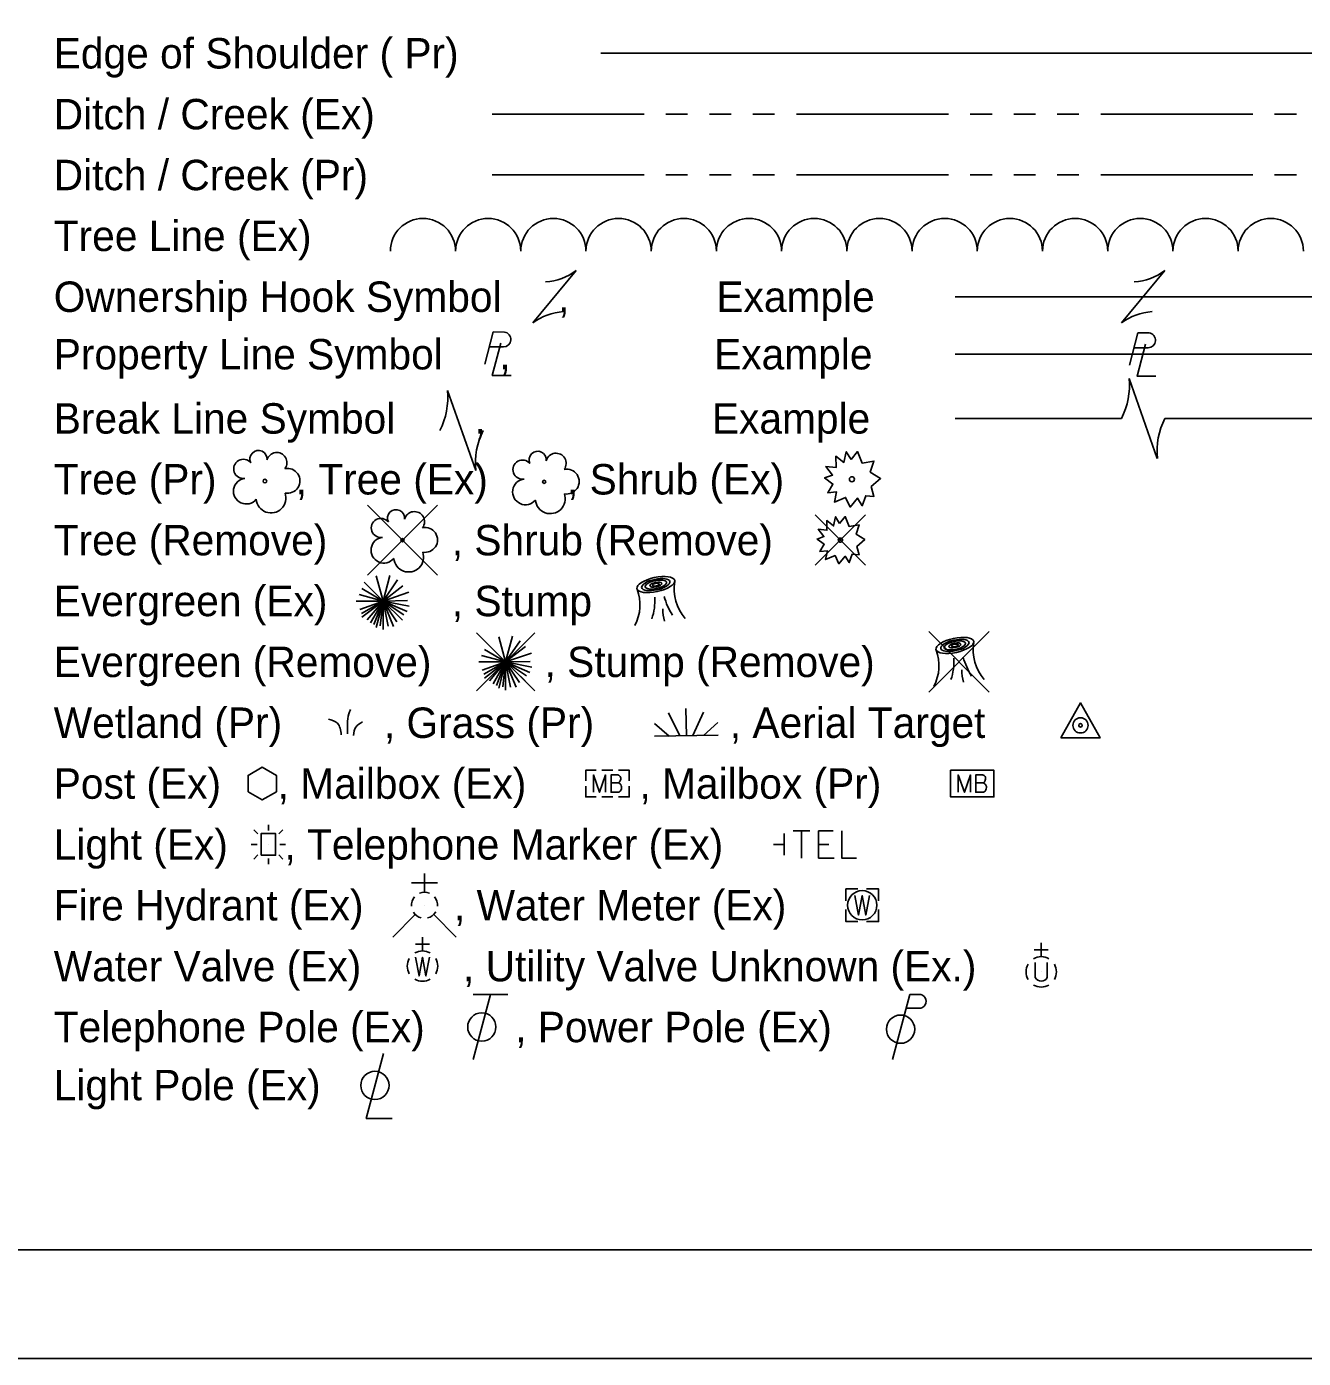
# Model space of a CAD drawing. Extents: x 0 to 34, y 0 to 22.
# Drawn here: x 8.61 to 14.48, y 0 to 6.13 of the extents above; entities that cross this region are included whole.
import ezdxf

# ---------------------------------------------------------------- set-up
doc = ezdxf.new("R2010")
doc.units = 0
for name, color, linetype in [('SH_Border', 7, 'Continuous'), ('SH_Cut_Line', 7, 'Continuous'), ('SH_Text', 7, 'Continuous')]:
    doc.layers.add(name, color=color, linetype=linetype)

msp = doc.modelspace()

# ---------------------------------------------------------------- linework, layer by layer
at = {"layer": 'SH_Border'}
msp.add_lwpolyline([(1.5, 21.5), (33.5, 21.5), (33.5, 0.5), (1.5, 0.5)], close=True, dxfattribs=at)
at = {"layer": 'SH_Cut_Line'}
msp.add_lwpolyline([(0, 0), (34, 0), (34, 22), (0, 22)], close=True, dxfattribs=at)
at = {"layer": 'SH_Text'}
for p, q in [((11.2493, 6.0046), (14.7327, 6.0046)), ((10.7489, 5.7246), (11.4489, 5.7246)), ((11.5489, 5.7246), (11.6489, 5.7246)), ((11.7489, 5.7246), (11.8489, 5.7246)), ((11.9489, 5.7246), (12.0489, 5.7246)), ((12.1489, 5.7246), (12.8489, 5.7246)), ((12.9489, 5.7246), (13.0489, 5.7246)), ((13.1489, 5.7246), (13.2489, 5.7246)), ((13.3489, 5.7246), (13.4489, 5.7246)), ((13.5489, 5.7246), (14.2489, 5.7246)), ((14.3489, 5.7246), (14.4489, 5.7246)), ((10.7489, 5.4446), (11.4489, 5.4446)), ((11.5489, 5.4446), (11.6489, 5.4446)), ((11.7489, 5.4446), (11.8489, 5.4446)), ((11.9489, 5.4446), (12.0489, 5.4446)), ((12.1489, 5.4446), (12.8489, 5.4446)), ((12.9489, 5.4446), (13.0489, 5.4446)), ((13.1489, 5.4446), (13.2489, 5.4446)), ((13.3489, 5.4446), (13.4489, 5.4446)), ((13.5489, 5.4446), (14.2489, 5.4446)), ((14.3489, 5.4446), (14.4489, 5.4446)), ((10.9362, 4.7646), (11.1362, 5.0046)), ((13.6444, 4.7646), (13.8444, 5.0046)), ((11.0362, 4.8846), (11.0362, 4.8846)), ((12.879, 4.8846), (14.6613, 4.8846)), ((13.7444, 4.8846), (13.7444, 4.8846)), ((10.7365, 4.6536), (10.8013, 4.6536)), ((10.7766, 4.6224), (10.7766, 4.6224)), ((12.879, 4.62), (14.6613, 4.62)), ((13.7021, 4.6495), (13.767, 4.6495)), ((13.7422, 4.6183), (13.7422, 4.6183)), ((13.6794, 4.5088), (13.8094, 4.1405)), ((10.5438, 4.4531), (10.6738, 4.0849)), ((12.879, 4.3246), (13.6445, 4.3246)), ((13.7444, 4.3247), (13.7444, 4.3247)), ((13.8444, 4.3246), (14.6613, 4.3246)), ((10.6088, 4.269), (10.6088, 4.269)), ((10.1766, 3.9249), (10.4974, 3.6042)), ((10.4974, 3.9249), (10.1766, 3.6042)), ((12.2357, 3.8805), (12.4675, 3.6487)), ((12.4675, 3.8805), (12.2357, 3.6487)), ((10.337, 3.7646), (10.337, 3.7646)), ((12.3516, 3.7646), (12.3516, 3.7646)), ((10.2475, 3.4844), (10.1602, 3.5715)), ((10.2475, 3.4844), (10.2166, 3.5997)), ((10.2475, 3.4844), (10.2789, 3.6018)), ((10.2475, 3.4844), (10.3139, 3.5815)), ((10.2475, 3.4844), (10.3389, 3.5545)), ((10.2475, 3.4844), (10.1372, 3.5139)), ((10.2475, 3.4844), (10.1498, 3.5418)), ((10.2475, 3.4844), (10.3659, 3.5245)), ((10.1241, 3.4844), (10.2475, 3.4844)), ((10.2475, 3.4844), (10.1402, 3.4453)), ((10.2475, 3.4844), (10.1479, 3.4273)), ((10.2475, 3.4844), (10.1498, 3.4095)), ((10.2475, 3.4844), (10.1739, 3.3977)), ((10.2475, 3.4844), (10.1895, 3.384)), ((10.2475, 3.4844), (10.2059, 3.3759)), ((10.2475, 3.4844), (10.2159, 3.3629)), ((10.2475, 3.4844), (10.2339, 3.3696)), ((10.2475, 3.4844), (10.3602, 3.4867)), ((10.2475, 3.3534), (10.2475, 3.4844)), ((10.2475, 3.4844), (10.2705, 3.3684)), ((10.2475, 3.4844), (10.2958, 3.3677)), ((10.2475, 3.4844), (10.3109, 3.3895)), ((10.2475, 3.4844), (10.3372, 3.3963)), ((10.2475, 3.4844), (10.343, 3.4205)), ((10.2475, 3.4844), (10.3591, 3.4358)), ((10.2475, 3.4844), (10.3682, 3.4604)), ((11.5211, 3.4846), (11.5211, 3.4846)), ((10.6779, 3.3382), (10.9452, 3.0709)), ((10.9452, 3.3382), (10.6779, 3.0709)), ((10.8115, 3.2046), (10.7806, 3.3199)), ((10.8115, 3.2046), (10.8429, 3.3221)), ((12.7577, 3.3436), (13.0358, 3.0655)), ((13.0358, 3.3436), (12.7577, 3.0655)), ((10.8115, 3.2046), (10.7138, 3.262)), ((10.8115, 3.2046), (10.7242, 3.2918)), ((10.8115, 3.2046), (10.8779, 3.3017)), ((10.8115, 3.2046), (10.9029, 3.2747)), ((10.6881, 3.2046), (10.8115, 3.2046)), ((10.8115, 3.2046), (10.7012, 3.2342)), ((10.8115, 3.2046), (10.7042, 3.1656)), ((10.8115, 3.2046), (10.7119, 3.1476)), ((10.8115, 3.2046), (10.7138, 3.1297)), ((10.8115, 3.2046), (10.7379, 3.1179)), ((10.8115, 3.2046), (10.7535, 3.1042)), ((10.8115, 3.2046), (10.7699, 3.0961)), ((10.8115, 3.2046), (10.7799, 3.0832)), ((10.8115, 3.2046), (10.798, 3.0898)), ((10.8115, 3.2046), (10.9299, 3.2448)), ((10.8115, 3.2046), (10.9242, 3.2069)), ((10.8115, 3.0736), (10.8115, 3.2046)), ((10.8115, 3.2046), (10.8345, 3.0887)), ((10.8115, 3.2046), (10.8598, 3.0879)), ((10.8115, 3.2046), (10.8749, 3.1098)), ((10.8115, 3.2046), (10.9012, 3.1166)), ((10.8115, 3.2046), (10.907, 3.1407)), ((10.8115, 3.2046), (10.9231, 3.1561)), ((10.8115, 3.2046), (10.9322, 3.1806)), ((10.8115, 3.2046), (10.8115, 3.2046)), ((12.8967, 3.2046), (12.8967, 3.2046)), ((12.8967, 3.2046), (12.8967, 3.2046)), ((11.6131, 2.8642), (11.561, 2.9702)), ((11.6431, 2.8646), (11.6412, 2.9901)), ((11.6731, 2.865), (11.722, 2.9726)), ((11.5644, 2.8634), (11.4961, 2.9205)), ((11.7218, 2.8658), (11.7884, 2.9249)), ((11.497, 2.8624), (11.7892, 2.8668)), ((11.2543, 2.7057), (11.3044, 2.7057)), ((11.2799, 2.6446), (11.2799, 2.6446)), ((12.958, 2.6446), (12.958, 2.6446)), ((11.2543, 2.5835), (11.3044, 2.5835)), ((9.7202, 2.4286), (9.7202, 2.4552)), ((9.6719, 2.413), (9.6534, 2.4318)), ((9.7869, 2.4318), (9.7683, 2.413)), ((12.0928, 2.3146), (12.0928, 2.4146)), ((9.668, 2.3649), (9.6414, 2.3649)), ((9.7202, 2.3646), (9.7202, 2.3646)), ((9.7989, 2.3649), (9.7723, 2.3649)), ((12.0928, 2.3646), (12.0431, 2.3646)), ((9.6719, 2.3162), (9.6534, 2.2974)), ((9.7202, 2.3006), (9.7202, 2.274)), ((9.7869, 2.2974), (9.7683, 2.3162)), ((10.4382, 2.1448), (10.4382, 2.2308)), ((10.4982, 2.1878), (10.3782, 2.1878)), ((10.4383, 2.0846), (10.4383, 2.0846)), ((10.4383, 2.0846), (10.4383, 2.0846)), ((12.4519, 2.0846), (12.4519, 2.0846)), ((10.396, 2.0422), (10.292, 1.9383)), ((10.4806, 2.0422), (10.5846, 1.9383)), ((10.4609, 1.9064), (10.3973, 1.9064)), ((10.4292, 1.8746), (10.4292, 1.9382)), ((13.2753, 1.8482), (13.2753, 1.9117)), ((13.3071, 1.88), (13.2435, 1.88)), ((10.4292, 1.8046), (10.4292, 1.8046)), ((13.2481, 1.8213), (13.2481, 1.7524)), ((13.2753, 1.7782), (13.2753, 1.7782)), ((13.3024, 1.8213), (13.3024, 1.7524)), ((10.7422, 1.6746), (10.6619, 1.3746)), ((10.8222, 1.6746), (10.6622, 1.6746)), ((12.6712, 1.6746), (12.5908, 1.3746)), ((12.6712, 1.6746), (12.7137, 1.6746)), ((12.6541, 1.6108), (12.7137, 1.6108))]:
    msp.add_line(p, q, dxfattribs=at)
for points in [[(10.7155, 4.574), (10.7546, 4.7223), (10.8063, 4.7222)], [(13.6811, 4.5699), (13.7202, 4.7182), (13.7719, 4.7181)], [(10.7899, 4.6704), (10.7503, 4.5226), (10.8377, 4.5226)], [(13.7556, 4.6663), (13.716, 4.5185), (13.8033, 4.5185)], [(12.4003, 4.1351), (12.4306, 4.1718), (12.4513, 4.1192), (12.5059, 4.1282), (12.489, 4.0776), (12.5363, 4.0478), (12.4934, 4.0111), (12.5059, 3.9654), (12.4683, 3.9688), (12.452, 3.9232), (12.4306, 3.9578), (12.3967, 3.9169), (12.3753, 3.9613), (12.3243, 3.9398), (12.3338, 3.9868), (12.2933, 3.9827), (12.3169, 4.0222), (12.2785, 4.0506), (12.3154, 4.0638), (12.2851, 4.1039), (12.3317, 4.0984), (12.3302, 4.1503), (12.3678, 4.1219), (12.3782, 4.1712), (12.4003, 4.1351)], [(12.348, 3.8415), (12.3737, 3.8728), (12.3913, 3.828), (12.4377, 3.8356), (12.4234, 3.7926), (12.4635, 3.7674), (12.4271, 3.7361), (12.4377, 3.6973), (12.4057, 3.7002), (12.3919, 3.6614), (12.3737, 3.6908), (12.3449, 3.6561), (12.3267, 3.6938), (12.2833, 3.6755), (12.2915, 3.7155), (12.257, 3.712), (12.2771, 3.7455), (12.2444, 3.7697), (12.2758, 3.7809), (12.25, 3.815), (12.2896, 3.8104), (12.2884, 3.8545), (12.3204, 3.8303), (12.3292, 3.8722), (12.348, 3.8415)], [(9.627, 2.6071), (9.6919, 2.5696), (9.7568, 2.6071), (9.7568, 2.6821), (9.6919, 2.7196), (9.627, 2.6821), (9.627, 2.6071)], [(11.1799, 2.6572), (11.1799, 2.7057), (11.2284, 2.7057)], [(11.3302, 2.7057), (11.3799, 2.7057), (11.3799, 2.6572)], [(11.215, 2.6046), (11.215, 2.6846), (11.244, 2.6046), (11.2717, 2.6846), (11.2717, 2.6046)], [(11.3309, 2.6481), (11.3341, 2.6512), (11.336, 2.6531), (11.3372, 2.655), (11.3379, 2.6562), (11.3391, 2.6588), (11.3398, 2.6607), (11.341, 2.6651), (11.341, 2.667), (11.341, 2.6695), (11.3404, 2.6733), (11.3391, 2.6764), (11.3372, 2.6789), (11.3341, 2.6814), (11.3316, 2.6827), (11.3303, 2.6833), (11.3272, 2.6846), (11.2963, 2.6846), (11.2963, 2.6046), (11.3309, 2.6046), (11.3353, 2.6071), (11.3391, 2.6103), (11.3423, 2.6153), (11.3442, 2.621), (11.3448, 2.6266), (11.3448, 2.6304), (11.3435, 2.6342), (11.341, 2.6399), (11.3379, 2.6436), (11.3309, 2.6481), (11.2963, 2.6481)], [(12.8932, 2.6046), (12.8932, 2.6846), (12.9221, 2.6046), (12.9498, 2.6846), (12.9498, 2.6046)], [(13.0091, 2.6481), (13.0122, 2.6512), (13.0141, 2.6531), (13.0154, 2.655), (13.016, 2.6562), (13.0173, 2.6588), (13.0179, 2.6607), (13.0191, 2.6651), (13.0191, 2.667), (13.0191, 2.6695), (13.0185, 2.6733), (13.0173, 2.6764), (13.0154, 2.6789), (13.0122, 2.6814), (13.0097, 2.6827), (13.0084, 2.6833), (13.0053, 2.6846), (12.9744, 2.6846), (12.9744, 2.6046), (13.0091, 2.6046), (13.0135, 2.6071), (13.0173, 2.6103), (13.0204, 2.6153), (13.0223, 2.621), (13.0229, 2.6266), (13.0229, 2.6304), (13.0217, 2.6342), (13.0191, 2.6399), (13.016, 2.6436), (13.0091, 2.6481), (12.9744, 2.6481)], [(11.2284, 2.5835), (11.1799, 2.5835), (11.1799, 2.632)], [(11.3799, 2.632), (11.3799, 2.5835), (11.3302, 2.5835)], [(12.1337, 2.4267), (12.2114, 2.4267)], [(12.173, 2.4267), (12.173, 2.3017)], [(12.3187, 2.4267), (12.2508, 2.4267), (12.2508, 2.3017), (12.3236, 2.3017)], [(12.358, 2.4267), (12.358, 2.3017), (12.426, 2.3017)], [(12.2508, 2.3647), (12.299, 2.3647)], [(12.4319, 2.1596), (12.3769, 2.1596), (12.3769, 2.1046)], [(12.5269, 2.1046), (12.5269, 2.1596), (12.4719, 2.1596)], [(12.4185, 2.1296), (12.4352, 2.0396), (12.4519, 2.1296), (12.4685, 2.0396), (12.4852, 2.1296)], [(12.3769, 2.0646), (12.3769, 2.0096), (12.4319, 2.0096)], [(12.4719, 2.0096), (12.5269, 2.0096), (12.5269, 2.0646)], [(10.3973, 1.8456), (10.4132, 1.7594), (10.4292, 1.8456), (10.4452, 1.7594), (10.461, 1.8456)], [(10.2494, 1.4033), (10.1707, 1.1041), (10.2889, 1.1041)]]:
    msp.add_lwpolyline(points, dxfattribs=at)
for points in [[(13.3661, 2.8546), (13.5461, 2.8546), (13.4561, 3.0156)], [(12.858, 2.7057), (13.058, 2.7057), (13.058, 2.5835), (12.858, 2.5835)], [(9.6869, 2.3146), (9.7534, 2.3146), (9.7534, 2.4146), (9.6869, 2.4146)]]:
    msp.add_lwpolyline(points, close=True, dxfattribs=at)
for centre, radius in [((9.704, 4.0365), 0.0084), ((12.4046, 4.0446), 0.0115), ((10.9886, 4.033), 0.0072), ((10.337, 3.7646), 0.0072), ((12.3516, 3.7646), 0.00979), ((13.4561, 2.9124), 0.035), ((13.4561, 2.9124), 0.008), ((12.4519, 2.0846), 0.0675), ((10.702, 1.5246), 0.065), ((12.6283, 1.5146), 0.065), ((10.2101, 1.2557), 0.065)]:
    msp.add_circle(centre, radius, dxfattribs=at)
for centre, radius, start, end in [((10.4312, 5.0946), 0.15, 0.00982, 179.99264), ((10.7312, 5.0946), 0.15, 0.00982, 179.99264), ((11.0312, 5.0946), 0.15, 0.00982, 179.99264), ((11.3312, 5.0946), 0.15, 0.00982, 179.99264), ((11.6312, 5.0946), 0.15, 0.00982, 179.99264), ((11.9312, 5.0946), 0.15, 0.00982, 179.99264), ((12.2312, 5.0946), 0.15, 0.00982, 179.99264), ((12.5312, 5.0946), 0.15, 0.00982, 179.99264), ((12.8312, 5.0946), 0.15, 0.00982, 179.99264), ((13.1312, 5.0946), 0.15, 0.00982, 179.99264), ((13.4312, 5.0946), 0.15, 0.00982, 179.99264), ((13.7312, 5.0946), 0.15, 0.00982, 179.99264), ((14.0312, 5.0946), 0.15, 0.00982, 179.99264), ((14.3312, 5.0946), 0.15, 0.00982, 179.99264), ((10.9781, 5.2195), 0.2668, 273.69448, 306.33701), ((13.6863, 5.2195), 0.2668, 273.69448, 306.33701), ((11.0943, 4.5496), 0.2668, 93.69448, 126.33701), ((13.8025, 4.5496), 0.2668, 93.69448, 126.33701), ((10.8011, 4.6881), 0.0345, 270.47098, 81.3281), ((13.7667, 4.684), 0.0345, 270.47098, 81.3281), ((13.3475, 4.4763), 0.3335, 332.94224, 5.58476), ((10.2118, 4.4207), 0.3335, 332.94224, 5.58476), ((14.1414, 4.173), 0.3335, 152.94224, 185.58476), ((11.0057, 4.1174), 0.3335, 152.94224, 185.58476), ((9.6745, 4.1375), 0.0395, 354.0047, 205.97412), ((9.7588, 4.1214), 0.0466, 323.82996, 165.0376), ((10.9591, 4.1341), 0.0395, 354.0047, 205.97412), ((9.6047, 4.0924), 0.0441, 39.06254, 279.54124), ((10.8893, 4.089), 0.0441, 39.06254, 279.54124), ((11.0434, 4.1179), 0.0466, 323.82996, 165.0376), ((9.6184, 3.99), 0.0592, 96.17219, 320.57371), ((9.8078, 4.0376), 0.0574, 259.14531, 101.45961), ((10.903, 3.9866), 0.0592, 96.17219, 320.57371), ((11.0924, 4.0341), 0.0574, 259.14531, 101.45961), ((9.7324, 3.9583), 0.0685, 184.94757, 19.45715), ((11.017, 3.9549), 0.0685, 184.94757, 19.45715), ((10.2377, 3.8205), 0.0441, 39.06254, 279.54124), ((10.3075, 3.8656), 0.0395, 354.0047, 205.97412), ((10.3918, 3.8494), 0.0466, 323.82996, 165.0376), ((10.4408, 3.7656), 0.0574, 259.14531, 101.45961), ((10.2514, 3.7181), 0.0592, 96.17219, 320.57371), ((10.3654, 3.6864), 0.0685, 184.94757, 19.45715), ((11.8014, 3.5416), 0.2146, 171.41061, 219.91939), ((11.2296, 3.4673), 0.2001, 331.53375, 20.92689), ((11.2453, 3.4859), 0.2527, 340.79377, 3.54808), ((11.8465, 3.5874), 0.316, 194.9653, 212.12159), ((11.7164, 3.4446), 0.1819, 178.79264, 197.12241), ((12.6051, 3.1873), 0.2001, 331.53375, 20.92689), ((13.177, 3.2616), 0.2146, 171.41061, 219.91939), ((12.6209, 3.2059), 0.2527, 340.79377, 3.54808), ((13.2221, 3.3074), 0.316, 194.9653, 212.12159), ((13.092, 3.1646), 0.1819, 178.79264, 197.12241), ((10.4383, 2.0846), 0.06, 68.13946, 112.03798), ((10.4383, 2.0846), 0.06, 140.02099, 184.06293), ((10.4383, 2.0846), 0.06, 356.01648, 39.98885), ((10.4383, 2.0846), 0.06, 211.87877, 255.84793), ((10.4383, 2.0846), 0.06, 283.82389, 329.90967), ((10.4291, 1.8047), 0.07, 150.01836, 209.98164), ((10.4291, 1.8047), 0.07, 60.01836, 120.01574), ((10.4291, 1.8047), 0.07, 330.01836, 29.98164), ((13.2753, 1.7782), 0.07, 60.01836, 120.01574), ((13.2753, 1.7782), 0.07, 150.01836, 209.98164), ((13.2753, 1.7782), 0.07, 330.01836, 29.98164), ((10.4291, 1.8047), 0.07, 239.98426, 299.98164), ((13.2753, 1.7782), 0.07, 239.98426, 299.98164), ((13.2753, 1.7651), 0.03, 205.19243, 334.80757), ((12.7143, 1.6427), 0.0319, 268.8767, 91.1233)]:
    msp.add_arc(centre, radius, start, end, dxfattribs=at)
for centre, major_axis in [((11.5024, 3.5601), (0.0868, 0.0187)), ((11.5024, 3.5601), (0.0651, 0.0141)), ((11.5024, 3.5601), (0.0488, 0.0105)), ((11.5024, 3.5601), (0.0275, 0.0059)), ((11.5024, 3.5601), (0.0154, 0.0033)), ((12.878, 3.2801), (0.0868, 0.0187)), ((12.878, 3.2801), (0.0651, 0.0141)), ((12.878, 3.2801), (0.0488, 0.0105)), ((12.878, 3.2801), (0.0275, 0.0059)), ((12.878, 3.2801), (0.0154, 0.0033))]:
    msp.add_ellipse(centre, major_axis=major_axis, ratio=0.36865, dxfattribs=at)
for points in [[(10.0836, 2.8732), (10.0836, 2.9205), (10.0895, 2.9649), (10.0983, 2.9857)], [(9.9962, 2.9402), (10.0376, 2.9225), (10.0554, 2.8692)], [(10.1113, 2.866), (10.1231, 2.9044), (10.1526, 2.9282)]]:
    msp.add_spline(points, degree=3, dxfattribs=at)

# ---------------------------------------------------------------- texts
for s, p in [('Edge of Shoulder ( Pr)', (8.7327, 5.9346)), ('Ditch / Creek (Ex)', (8.7327, 5.6546)), ('Ditch / Creek (Pr)', (8.7327, 5.3746)), ('Tree Line (Ex)', (8.7327, 5.0946)), ('Ownership Hook Symbol     ,             Example', (8.7327, 4.8146)), ('Property Line Symbol     ,                  Example', (8.7327, 4.55)), ('Break Line Symbol       ,                    Example', (8.7327, 4.2546)), ('Tree (Pr)       , Tree (Ex)       , Shrub (Ex)', (8.7327, 3.9746)), ('Tree (Remove)           , Shrub (Remove)', (8.7327, 3.6946)), ('Evergreen (Ex)           , Stump ', (8.7327, 3.4146)), ('Evergreen (Remove)          , Stump (Remove)', (8.7327, 3.1346)), ('Wetland (Pr)         , Grass (Pr)            , Aerial Target    ', (8.7327, 2.8546)), ('Post (Ex)     , Mailbox (Ex)          , Mailbox (Pr)', (8.7327, 2.5746)), ('Light (Ex)     , Telephone Marker (Ex)     ', (8.7327, 2.2946)), ('Fire Hydrant (Ex)        , Water Meter (Ex)', (8.7327, 2.0146)), ('Water Valve (Ex)         , Utility Valve Unknown (Ex.)', (8.7327, 1.7346)), ('Telephone Pole (Ex)        , Power Pole (Ex)', (8.7327, 1.4546)), ('Light Pole (Ex)     ', (8.7327, 1.1875))]:
    msp.add_text(s, height=0.14, dxfattribs=at).set_placement(p)

doc.saveas('drawing.dxf')
